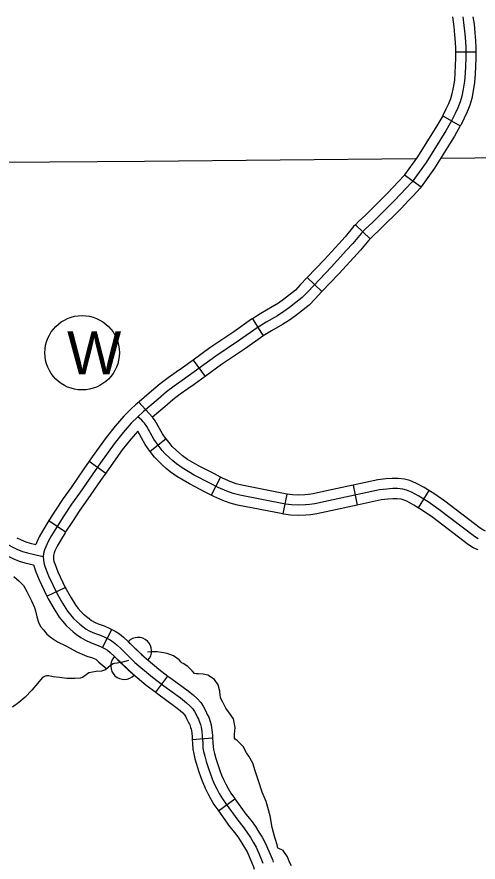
# Model space of a CAD drawing. Extents: x -3711 to 825, y -151 to 1050.
# Drawn here: x -2703.9 to -2665.8, y 442 to 512 of the extents above; entities that cross this region are included whole.
import ezdxf

# ---------------------------------------------------------------- set-up
doc = ezdxf.new("R2010")
doc.units = 0
for name, color, linetype in [('Level 32', 7, 'Continuous'), ('Level 35', 7, 'Continuous'), ('Level 38', 7, 'Continuous'), ('Level 5', 7, 'Continuous'), ('Level 57', 7, 'Continuous')]:
    doc.layers.add(name, color=color, linetype=linetype)

msp = doc.modelspace()

# ---------------------------------------------------------------- linework, layer by layer
at = {"layer": 'Level 32'}
for p, q in [((-2667.617, 509.095), (-2665.936, 509.095)), ((-2668.688, 503.794), (-2667.227, 502.963)), ((-2671.834, 498.896), (-2670.472, 497.91)), ((-2675.905, 494.767), (-2674.694, 493.601)), ((-2679.895, 490.397), (-2678.682, 489.233)), ((-2684.435, 486.985), (-2683.539, 485.563)), ((-2689.333, 483.563), (-2688.341, 482.205)), ((-2693.838, 480.088), (-2692.7, 478.851)), ((-2691.572, 477.034), (-2692.893, 475.994)), ((-2697.945, 475.19), (-2696.573, 474.218)), ((-2687.07, 473.877), (-2687.845, 472.385)), ((-2676.104, 473.209), (-2675.752, 471.565)), ((-2681.594, 472.477), (-2681.917, 470.827)), ((-2669.824, 472.768), (-2670.704, 471.335)), ((-2701.295, 470.277), (-2699.89, 469.354)), ((-2701.438, 464.032), (-2699.918, 464.75)), ((-2696.847, 459.78), (-2696.073, 461.273)), ((-2692.44, 456.069), (-2691.427, 457.411)), ((-2689.407, 452.169), (-2687.73, 452.289)), ((-2687.244, 446.261), (-2685.876, 447.238))]:
    msp.add_line(p, q, dxfattribs=at)
for points in [[(-2667.027, 511.974), (-2666.926, 511.261), (-2666.858, 510.565), (-2666.803, 509.924), (-2666.776, 509.42), (-2666.776, 508.547), (-2666.831, 507.292), (-2666.885, 506.651), (-2666.981, 505.996), (-2667.103, 505.41), (-2667.24, 504.932), (-2667.43, 504.455), (-2667.662, 503.964), (-2667.935, 503.418), (-2668.439, 502.532), (-2670.061, 499.913), (-2671.206, 498.331), (-2671.751, 497.744), (-2672.146, 497.321), (-2672.705, 496.735), (-2674.49, 494.962), (-2675.063, 494.43), (-2675.431, 494.048), (-2676.126, 493.216), (-2676.671, 492.629), (-2677.884, 491.279), (-2679.86, 489.22), (-2680.31, 488.742), (-2681.359, 487.91), (-2681.823, 487.583), (-2682.368, 487.242), (-2683.295, 486.71), (-2684.031, 486.246), (-2685.489, 485.21), (-2687.465, 483.887), (-2689.741, 482.223), (-2690.259, 481.882), (-2690.9, 481.418), (-2691.54, 480.94), (-2692.235, 480.34), (-2693.45, 479.318), (-2693.925, 478.881), (-2694.469, 478.351), (-2695.138, 477.558), (-2695.874, 476.644), (-2697.006, 475.062), (-2697.701, 474.08), (-2698.75, 472.552), (-2699.404, 471.625), (-2700.031, 470.67), (-2700.658, 469.715), (-2701.053, 469.033), (-2701.326, 468.542), (-2701.544, 468.106), (-2701.639, 467.86), (-2701.721, 467.56), (-2701.749, 467.307), (-2701.735, 466.974), (-2701.667, 466.66), (-2701.558, 466.346), (-2701.299, 465.705), (-2700.59, 464.205), (-2700.154, 463.441), (-2699.731, 462.773), (-2699.5, 462.473), (-2699.241, 462.173), (-2698.982, 461.941), (-2698.709, 461.709), (-2698.478, 461.504)], [(-2667.876, 511.974), (-2667.761, 511.161), (-2667.695, 510.489), (-2667.642, 509.866), (-2667.617, 509.397), (-2667.617, 509.095)], [(-2666.178, 511.974), (-2666.091, 511.361), (-2666.021, 510.642), (-2665.965, 509.983), (-2665.936, 509.442), (-2665.936, 509.095)], [(-2667.617, 509.095), (-2667.617, 508.565), (-2667.67, 507.346), (-2667.721, 506.747), (-2667.809, 506.143), (-2667.92, 505.611), (-2668.036, 505.204), (-2668.201, 504.791), (-2668.418, 504.331), (-2668.676, 503.814), (-2668.688, 503.794)], [(-2665.936, 509.095), (-2665.936, 508.528), (-2665.992, 507.238), (-2666.05, 506.554), (-2666.152, 505.849), (-2666.287, 505.208), (-2666.443, 504.66), (-2666.659, 504.119), (-2666.906, 503.597), (-2667.193, 503.022), (-2667.227, 502.963)], [(-2668.688, 503.794), (-2669.162, 502.961), (-2670.759, 500.381), (-2671.834, 498.896)], [(-2667.227, 502.963), (-2667.716, 502.102), (-2669.362, 499.445), (-2670.472, 497.91)], [(-2671.834, 498.896), (-2671.856, 498.865), (-2672.366, 498.317), (-2672.757, 497.898), (-2673.305, 497.323), (-2675.073, 495.568), (-2675.652, 495.03), (-2675.905, 494.767)], [(-2670.472, 497.91), (-2670.555, 497.796), (-2671.136, 497.171), (-2671.535, 496.744), (-2672.104, 496.147), (-2673.908, 494.356), (-2674.473, 493.83), (-2674.694, 493.601)], [(-2675.905, 494.767), (-2676.057, 494.61), (-2676.757, 493.772), (-2677.291, 493.197), (-2678.5, 491.851), (-2679.895, 490.397)], [(-2674.694, 493.601), (-2674.805, 493.486), (-2675.495, 492.66), (-2676.05, 492.062), (-2677.268, 490.707), (-2678.682, 489.233)], [(-2679.895, 490.397), (-2680.469, 489.799), (-2680.88, 489.363), (-2681.863, 488.583), (-2682.288, 488.283), (-2682.8, 487.963), (-2683.728, 487.43), (-2684.435, 486.985)], [(-2678.682, 489.233), (-2679.251, 488.64), (-2679.74, 488.121), (-2680.855, 487.237), (-2681.357, 486.883), (-2681.936, 486.521), (-2682.861, 485.989), (-2683.539, 485.562)], [(-2684.435, 486.985), (-2684.499, 486.945), (-2685.966, 485.902), (-2687.947, 484.575), (-2689.333, 483.563)], [(-2683.539, 485.563), (-2683.563, 485.547), (-2685.012, 484.518), (-2686.983, 483.198), (-2688.341, 482.205)], [(-2689.333, 483.563), (-2690.221, 482.913), (-2690.737, 482.573), (-2691.397, 482.095), (-2692.067, 481.596), (-2692.781, 480.98), (-2694.005, 479.95), (-2694.079, 479.881)], [(-2688.341, 482.205), (-2689.262, 481.532), (-2689.781, 481.19), (-2690.402, 480.74), (-2691.014, 480.284), (-2691.69, 479.701), (-2692.7, 478.851)], [(-2694.079, 479.881), (-2694.503, 479.492), (-2695.085, 478.925), (-2695.787, 478.093), (-2696.544, 477.153), (-2697.691, 475.549), (-2697.945, 475.19)], [(-2665.756, 468.771), (-2666.061, 468.97), (-2669.018, 471.2), (-2669.893, 471.823), (-2670.649, 472.288), (-2671.272, 472.633), (-2671.683, 472.805), (-2671.988, 472.885), (-2672.413, 472.925), (-2672.824, 472.925), (-2673.301, 472.885), (-2673.911, 472.819), (-2678.128, 471.916), (-2679.256, 471.664), (-2679.693, 471.598), (-2680.051, 471.571), (-2680.582, 471.545), (-2681.205, 471.571), (-2681.683, 471.638), (-2685.475, 472.381), (-2686.032, 472.514), (-2686.549, 472.713), (-2687.266, 473.031), (-2687.955, 473.389), (-2689.242, 474.053), (-2690.249, 474.637), (-2690.727, 474.969), (-2691.019, 475.221), (-2691.324, 475.5), (-2691.668, 475.831), (-2691.894, 476.083), (-2692.239, 476.521), (-2692.583, 477.026), (-2693.18, 478.074), (-2693.363, 478.334), (-2693.464, 478.454), (-2693.599, 478.579), (-2693.925, 478.881)], [(-2691.561, 477.019), (-2691.87, 477.472), (-2692.47, 478.526), (-2692.7, 478.851)], [(-2693.928, 477.689), (-2694.49, 477.023), (-2695.205, 476.136), (-2696.321, 474.575), (-2696.573, 474.218)], [(-2692.893, 475.994), (-2692.916, 476.023), (-2693.297, 476.58), (-2693.928, 477.689)], [(-2687.07, 473.877), (-2687.569, 474.136), (-2688.838, 474.791), (-2689.798, 475.347), (-2690.211, 475.634), (-2690.46, 475.849), (-2690.749, 476.113), (-2691.063, 476.415), (-2691.25, 476.624), (-2691.572, 477.034)], [(-2687.845, 472.385), (-2688.342, 472.643), (-2689.645, 473.315), (-2690.701, 473.927), (-2691.243, 474.304), (-2691.577, 474.592), (-2691.899, 474.886), (-2692.274, 475.248), (-2692.538, 475.543), (-2692.893, 475.994)], [(-2697.945, 475.19), (-2698.39, 474.561), (-2699.44, 473.032), (-2700.099, 472.098), (-2700.734, 471.131), (-2701.295, 470.277)], [(-2696.573, 474.218), (-2697.011, 473.599), (-2698.06, 472.072), (-2698.709, 471.152), (-2699.329, 470.209), (-2699.89, 469.354)], [(-2681.594, 472.477), (-2685.297, 473.202), (-2685.783, 473.318), (-2686.227, 473.489), (-2686.901, 473.789), (-2687.07, 473.877)], [(-2669.824, 472.768), (-2670.225, 473.014), (-2670.905, 473.39), (-2671.413, 473.604), (-2671.842, 473.716), (-2672.373, 473.766), (-2672.859, 473.766), (-2673.382, 473.722), (-2674.045, 473.65), (-2676.104, 473.209)], [(-2711.159, 472.998), (-2710.932, 472.625), (-2710.738, 472.366), (-2710.447, 472.026), (-2710.172, 471.75), (-2709.896, 471.54), (-2709.443, 471.254), (-2706.497, 469.417), (-2705.105, 468.559), (-2704.328, 468.105), (-2703.923, 467.911), (-2703.453, 467.716), (-2703.046, 467.599), (-2702.369, 467.441), (-2701.749, 467.307)], [(-2676.104, 473.209), (-2678.308, 472.738), (-2679.411, 472.491), (-2679.788, 472.434), (-2680.103, 472.41), (-2680.585, 472.386), (-2681.129, 472.409), (-2681.544, 472.467), (-2681.594, 472.477)], [(-2681.917, 470.827), (-2685.654, 471.559), (-2686.282, 471.709), (-2686.871, 471.936), (-2687.631, 472.273), (-2687.845, 472.385)], [(-2665.131, 469.416), (-2665.19, 469.439), (-2665.353, 469.512), (-2665.577, 469.658), (-2668.521, 471.878), (-2669.429, 472.525), (-2669.824, 472.768)], [(-2675.752, 471.565), (-2677.949, 471.095), (-2679.101, 470.837), (-2679.599, 470.762), (-2679.999, 470.732), (-2680.579, 470.703), (-2681.281, 470.733), (-2681.821, 470.808), (-2681.917, 470.827)], [(-2670.704, 471.335), (-2671.073, 471.562), (-2671.64, 471.875), (-2671.954, 472.007), (-2672.135, 472.055), (-2672.452, 472.084), (-2672.789, 472.084), (-2673.221, 472.048), (-2673.778, 471.988), (-2675.752, 471.565)], [(-2665.756, 467.855), (-2665.844, 467.89), (-2666.159, 468.03), (-2666.544, 468.282), (-2669.515, 470.522), (-2670.358, 471.122), (-2670.704, 471.335)], [(-2701.295, 470.277), (-2701.374, 470.157), (-2701.785, 469.448), (-2702.07, 468.934), (-2702.313, 468.447), (-2702.369, 468.304)], [(-2703.924, 468.844), (-2703.58, 468.679), (-2703.175, 468.511), (-2702.834, 468.413), (-2702.369, 468.304)], [(-2699.89, 469.354), (-2699.943, 469.273), (-2700.322, 468.618), (-2700.582, 468.15), (-2700.775, 467.765), (-2700.84, 467.597), (-2700.893, 467.402), (-2700.907, 467.279), (-2700.898, 467.082), (-2700.856, 466.888), (-2700.771, 466.642), (-2700.528, 466.042), (-2699.918, 464.75)], [(-2704.652, 467.329), (-2704.266, 467.143), (-2703.732, 466.922), (-2703.258, 466.785), (-2702.542, 466.618)], [(-2702.542, 466.618), (-2702.345, 466.051), (-2702.069, 465.368), (-2701.438, 464.032)], [(-2699.918, 464.75), (-2699.844, 464.593), (-2699.433, 463.874), (-2699.042, 463.255), (-2698.848, 463.005), (-2698.64, 462.763), (-2698.429, 462.574), (-2698.159, 462.344), (-2697.954, 462.163), (-2697.739, 462.009), (-2697.499, 461.874), (-2697.196, 461.739), (-2696.707, 461.563), (-2696.221, 461.349), (-2696.072, 461.272)], [(-2701.438, 464.032), (-2701.336, 463.816), (-2700.875, 463.008), (-2700.421, 462.29), (-2700.151, 461.941), (-2699.842, 461.582), (-2699.535, 461.307), (-2699.26, 461.074), (-2699.002, 460.846), (-2698.644, 460.59), (-2698.256, 460.371), (-2697.824, 460.178), (-2697.331, 460), (-2696.946, 459.831), (-2696.847, 459.78)], [(-2698.478, 461.504), (-2698.191, 461.3), (-2697.878, 461.122), (-2697.51, 460.959), (-2697.019, 460.781), (-2696.583, 460.59), (-2696.215, 460.399), (-2695.929, 460.222), (-2695.656, 459.99), (-2695.302, 459.663), (-2694.811, 459.172), (-2694.157, 458.544), (-2692.699, 457.317), (-2691.758, 456.608), (-2690.382, 455.598), (-2689.878, 455.203), (-2689.605, 454.957), (-2689.387, 454.712), (-2689.237, 454.48), (-2689.128, 454.289), (-2688.992, 453.989), (-2688.908, 453.838), (-2688.829, 453.688), (-2688.739, 453.399), (-2688.678, 453.184), (-2688.624, 452.83), (-2688.583, 452.434), (-2688.542, 451.861), (-2688.528, 451.452), (-2688.474, 451.152), (-2688.378, 450.784), (-2688.256, 450.347), (-2688.092, 449.829), (-2687.915, 449.297), (-2687.765, 448.901), (-2687.588, 448.492), (-2687.383, 448.069), (-2687.179, 447.687), (-2686.92, 447.251), (-2686.607, 446.815), (-2685.652, 445.478), (-2685.216, 444.946), (-2684.889, 444.482), (-2684.603, 444.032), (-2684.358, 443.65), (-2684.126, 443.241), (-2683.853, 442.6), (-2683.567, 441.918)], [(-2696.073, 461.273), (-2695.8, 461.131), (-2695.432, 460.903), (-2695.099, 460.619), (-2694.719, 460.269), (-2694.223, 459.772), (-2693.595, 459.17), (-2692.175, 457.975), (-2691.427, 457.411)], [(-2696.847, 459.78), (-2696.631, 459.668), (-2696.425, 459.541), (-2696.214, 459.361), (-2695.885, 459.057), (-2695.4, 458.571), (-2694.719, 457.919), (-2693.223, 456.659), (-2692.44, 456.069)], [(-2691.427, 457.411), (-2691.257, 457.282), (-2689.874, 456.268), (-2689.336, 455.847), (-2689.008, 455.551), (-2688.716, 455.222), (-2688.518, 454.917), (-2688.379, 454.672), (-2688.24, 454.366), (-2688.169, 454.238), (-2688.049, 454.013), (-2687.933, 453.638), (-2687.855, 453.363), (-2687.79, 452.937), (-2687.745, 452.507), (-2687.73, 452.289)], [(-2692.44, 456.069), (-2692.26, 455.933), (-2690.89, 454.929), (-2690.419, 454.559), (-2690.202, 454.364), (-2690.058, 454.202), (-2689.955, 454.043), (-2689.877, 453.906), (-2689.744, 453.612), (-2689.648, 453.438), (-2689.608, 453.363), (-2689.545, 453.16), (-2689.501, 453.005), (-2689.458, 452.722), (-2689.42, 452.361), (-2689.407, 452.169)], [(-2689.407, 452.169), (-2689.381, 451.817), (-2689.366, 451.362), (-2689.295, 450.971), (-2689.19, 450.565), (-2689.061, 450.107), (-2688.892, 449.57), (-2688.707, 449.015), (-2688.544, 448.585), (-2688.352, 448.142), (-2688.133, 447.688), (-2687.911, 447.274), (-2687.624, 446.791), (-2687.29, 446.325), (-2687.244, 446.261)], [(-2687.73, 452.289), (-2687.702, 451.905), (-2687.69, 451.542), (-2687.652, 451.333), (-2687.567, 451.003), (-2687.45, 450.587), (-2687.292, 450.088), (-2687.123, 449.579), (-2686.986, 449.218), (-2686.823, 448.842), (-2686.634, 448.451), (-2686.447, 448.101), (-2686.216, 447.712), (-2685.923, 447.304), (-2685.876, 447.238)], [(-2685.876, 447.238), (-2684.985, 445.989), (-2684.547, 445.455), (-2684.191, 444.95), (-2683.895, 444.485), (-2683.638, 444.085), (-2683.371, 443.614), (-2683.079, 442.927), (-2682.784, 442.224), (-2682.706, 442.01)], [(-2687.244, 446.261), (-2686.32, 444.967), (-2685.886, 444.437), (-2685.588, 444.014), (-2685.311, 443.579), (-2685.078, 443.216), (-2684.881, 442.868), (-2684.628, 442.273), (-2684.351, 441.612), (-2684.287, 441.438)]]:
    msp.add_lwpolyline(points, dxfattribs=at)
at = {"layer": 'Level 35'}
for points in [[(-2704.177, 465.657), (-2703.764, 465.293), (-2703.384, 464.913), (-2703.103, 464.417), (-2702.723, 463.623), (-2702.459, 463.094), (-2702.376, 462.813), (-2702.277, 462.301), (-2702.145, 461.871), (-2701.963, 461.523), (-2701.732, 461.242), (-2701.434, 460.879), (-2701.054, 460.581), (-2700.559, 460.25), (-2699.881, 459.92), (-2698.906, 459.374), (-2698.146, 459.043), (-2697.667, 458.927), (-2697.386, 458.795), (-2697.138, 458.547), (-2696.481, 458.01)], [(-2681.187, 441.696), (-2681.357, 442.013), (-2681.543, 442.44), (-2681.894, 442.967), (-2682.312, 443.153), (-2682.315, 443.155), (-2682.323, 443.168), (-2682.384, 443.438), (-2682.519, 443.882), (-2682.576, 444.04), (-2682.787, 444.882), (-2682.957, 445.852), (-2683.306, 447.028), (-2683.626, 447.786), (-2683.929, 448.728), (-2684.205, 449.557), (-2684.387, 450.205), (-2684.732, 450.765), (-2684.919, 451.063), (-2685.202, 451.568), (-2685.687, 452.079), (-2685.849, 452.187), (-2685.905, 452.257), (-2685.916, 452.331), (-2685.905, 452.597), (-2685.862, 453.145), (-2685.995, 453.875), (-2686.402, 454.435), (-2686.637, 454.753), (-2686.886, 455.236), (-2687.058, 455.555), (-2687.078, 455.644), (-2687.103, 455.863), (-2687.125, 456.149), (-2687.26, 456.69), (-2687.579, 457.138), (-2688.122, 457.472), (-2688.523, 457.561), (-2688.882, 457.582), (-2689.098, 457.598), (-2689.214, 457.608), (-2689.411, 457.845), (-2689.773, 458.207), (-2690.167, 458.436), (-2690.245, 458.49), (-2690.321, 458.559), (-2690.499, 458.759), (-2690.964, 459.079), (-2691.493, 459.268), (-2691.953, 459.37), (-2692.327, 459.411), (-2692.723, 459.411), (-2693.118, 459.39)], [(-2694.7, 458.706), (-2694.894, 458.646), (-2695.176, 458.562), (-2695.475, 458.513), (-2695.624, 458.479), (-2695.873, 458.446), (-2695.956, 458.43), (-2696.172, 458.28), (-2696.371, 458.114), (-2696.604, 457.914), (-2696.936, 457.815), (-2697.368, 457.782), (-2697.965, 457.682), (-2698.198, 457.516), (-2698.497, 457.283), (-2698.696, 457.233), (-2699.144, 457.217), (-2699.792, 457.217), (-2700.389, 457.283), (-2700.921, 457.35), (-2701.269, 457.416), (-2701.485, 457.416), (-2701.651, 457.383), (-2701.817, 457.283), (-2701.983, 457.1), (-2702.216, 456.801), (-2702.697, 456.236), (-2703.245, 455.655), (-2703.776, 455.223), (-2704.291, 454.841)]]:
    msp.add_lwpolyline(points, dxfattribs=at)
at = {"layer": 'Level 38'}
for p, q in [((-2693.075, 458.718), (-2694.713, 460.249)), ((-2694.223, 457.49), (-2695.861, 459.021))]:
    msp.add_line(p, q, dxfattribs=at)
for centre, start, end in [((-2693.894, 459.484), 316.92706, 136.92706), ((-2695.042, 458.256), 136.92706, 316.92706)]:
    msp.add_arc(centre, 1.121, start, end, dxfattribs=at)
at = {"layer": 'Level 5'}
for points in [[(-2709.057, 499.916), (-2693.363, 500.029), (-2670.922, 500.253)], [(-2668.794, 500.275), (-2657.777, 500.384), (-2627.897, 499.858)]]:
    msp.add_lwpolyline(points, dxfattribs=at)
at = {"layer": 'Level 57'}
msp.add_circle((-2698.526, 484.172), 3.082, dxfattribs=at)

# ---------------------------------------------------------------- texts
msp.add_text('W', height=3.551, dxfattribs=at).set_placement((-2699.771, 482.397))

doc.saveas('drawing.dxf')
